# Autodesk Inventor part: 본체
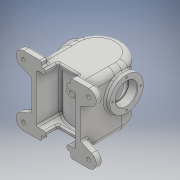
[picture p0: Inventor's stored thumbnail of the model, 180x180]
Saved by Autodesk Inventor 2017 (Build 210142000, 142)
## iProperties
Part Number: 본체
Material: 일반
Document SubType Name: Modeling
Designer: user
Density: 1 g/cm^3
Appearance: 기본값
Mass: 513.52 g
Surface Area: 1149.35 cm^2
Volume: 513.52 cm^3
Author: user
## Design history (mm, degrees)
sketch "스케치2"
  geometry: L1 (76, 0)-(76, -114); L2 (76, 0)-(121, 0); L3 (121, 0)-(121, -108); L4 (121, -108)-(104.5, -108); L5 (104.5, -108)-(104.5, -114); L6 (104.5, -114)-(92.5, -114); L7 (76, -9)-(112, -9); L8 (112, -9)-(112, -99); L9 (112, -99)-(92.5, -99); L10 (92.5, -99)-(92.5, -114); L11 (92.5, -114)-(76, -114); L12 (76, 0)-(76, -9); 1 further point
  constraints: 24 end point, 9 perpendicular, 2 horizontal, 1 collinear, 1 point on line, 1 vertical
  dimensions: "d3" = 76 distance from line of point (0, 0) L1; "d4" = 90 diameter of L3 L1; "d5" = 114 distance of L1.start L1.end; "d6" = 108 distance between parallel lines of L2 L4; "d7" = 57 diameter of L5 L1; "d8" = 0 distance from line of point (0, 0) L2; "d9" = 9 distance between parallel lines of L4 L9; "d10" = 9 distance between parallel lines of L2 L7; "d11" = 9 distance between parallel lines of L8 L3; "d12" = 33 diameter of L10 L1
revolve "회전1" sketch "스케치2" stored, may be unused: angle "d13" = 90 deg
node "작업 평면1"
sketch "스케치4"
  geometry: L1 (47.5, -114)-(104.5, -114) reference; C1 r 31 at (76, -40); 1 further point
  constraints: 1 centre point
  dimensions: "d15" = 62 diameter of C1; "d16" = 74 distance from line of L1 C1.centre; "d17" = 76 horizontal distance of point (0, 0) C1.centre
extrude "돌출1" join sketch "스케치4" stored distance "d18" = 10; taper "d19" = 0 deg
hole "구멍1" diameter "d22" = 35; stored, may be unused: countersink angle "d26" = 90 deg, drill point angle "d28" = 0 deg; dims "d20" = 10, "d21" = 10, "d23" = 6, "d24" = 40, "d25" = 16, "d27" = 8
node "작업 평면2"
sketch "스케치5"
  geometry: L1 (-28.5, -114)-(28.5, -114) reference; C1 r 7.5 at (0, -40); 1 further point
  constraints: 1 centre point, 1 vertical alignment
  dimensions: "d30" = 15 diameter of C1; "d31" = 74 distance from line of C1.centre L1
extrude "돌출2" join sketch "스케치5" stored distance "d32" = 10; taper "d33" = 0 deg
node "작업 평면3"
hole "구멍2" diameter "d37" = 5.188; stored, may be unused: countersink angle "d41" = 90 deg, drill point angle "d43" = 118 deg; dims "d35" = 10, "d36" = 10, "d38" = 12, "d39" = 40, "d40" = 16, "d42" = 16
sketch "스케치10" dims "d56" = 10, "d60" = 10
  geometry: L1 (74, 10)-(-74, 10); L2 (-74, 10)-(-74, -118); L3 (-74, -118)-(74, -118); L4 (74, -118)-(74, 10); L5 (-45, 0)-(45, 0) reference; L6 (60, 10)-(-60, 10); L7 (60, -118)-(-60, -118); L8 (74, -4)-(74, -104); L9 (-74, -4)-(-74, -104); A1 r 14 centre (60, -4) between (60, 10) and (74, -4); A2 r 14 centre (-60, -4) between (-60, 10) and (-74, -4); A3 r 14 centre (60, -104) between (60, -118) and (74, -104); A4 r 14 centre (-60, -104) between (-60, -118) and (-74, -104); 1 further point
  constraints: 16 end point, 8 point on circle, 8 point on line, 4 centre point, 2 horizontal, 2 parallel, 1 perpendicular, 1 vertical, 6 other
  dimensions: "d44" = 128 distance between parallel lines of L3 L1; "d45" = 148 distance of L1.start L1.end; "d46" = 74 distance from line of point (0, 0) L4; "d47" = 10 distance between parallel lines of L5 L1; "d48" = 28 diameter of A1; "d49" = 60 horizontal distance of point (0, 0) A1.centre; "d50" = 14 distance from line of L1 A1.centre; "d53" = 120 distance of A1.centre A2.centre; "d63" = 100 distance of A1.centre A3.centre
extrude "돌출3" join sketch "스케치10" distance "d65" = 12; taper "d66" = 0 deg
sketch "스케치13"
  geometry: L1 (74, 104)-(74, 4) reference; L2 (60, -10)-(-60, -10) reference; L3 (-74, 4)-(-74, 104) reference; L4 (-60, 118)-(60, 118) reference; L5 (-45, 0)-(45, 0); L6 (45, 0)-(45, 108); L7 (45, 108)-(-45, 108); L8 (-45, 108)-(-45, 0); L9 (-36, 9)-(36, 9); L10 (36, 9)-(36, 99); L11 (36, 99)-(-36, 99); L12 (-36, 99)-(-36, 9); A1 r 14 centre (60, 4) between (60, -10) and (74, 4) reference; A2 r 14 centre (-60, 4) between (-74, 4) and (-60, -10) reference; A3 r 14 centre (-60, 104) between (-60, 118) and (-74, 104) reference; A4 r 14 centre (60, 104) between (74, 104) and (60, 118) reference; 1 further point
  constraints: 16 end point, 4 parallel, 2 perpendicular, 1 horizontal, 3 other
  dimensions: "d67" = 10 distance between parallel lines of L2 L5; "d68" = 45 distance from line of point (0, 0) L8; "d69" = 45 distance from line of L6 point (0, 0); "d70" = 10 distance between parallel lines of L4 L7; "d71" = 9 distance between parallel lines of L8 L12
  node "절단 모서리 투영2"
extrude "돌출4" join sketch "스케치13" stored distance "d72" = 12; taper "d73" = 0 deg; dims "d3" = 76, "d4" = 90, "d5" = 114, "d6" = 108, "d7" = 57, "d8" = 0, "d9" = 9, "d10" = 9, "d11" = 9, "d12" = 33
sketch "스케치14"
  geometry: L1 (-78, -64)-(50, -64) reference; L2 (50, -64)-(50, -76) reference; L3 (50, -76)-(-78, -76) reference; L4 (-78, -76)-(-78, -64) reference; C1 r 31 at (0, 0) reference; C2 r 20 at (0, 0) reference; 1 further point
hole "구멍3" sketch "스케치14" at (0, 0) diameter "d74" = 40; stored, may be unused: countersink angle "d78" = 90 deg, drill point angle "d80" = 0 deg; dims "d75" = 12, "d76" = 40, "d77" = 16, "d79" = 16
extrude "돌출5" cut sketch "스케치13" stored distance "d81" = 12; taper "d82" = 0 deg
fillet "모깎기1" dims "d83" = 12
sketch "스케치15"
  geometry: L1 (40, -23)-(80, -23); L2 (80, -23)-(80, 23); L3 (80, 23)-(40, 23); L4 (40, 23)-(40, -23); L5 (40, -23)-(80, 23); L6 (80, -23)-(40, 23); L7 (0, 0)-(120, 0) reference; 1 further point
  constraints: 12 end point, 2 midpoint, 2 parallel, 1 horizontal, 1 perpendicular
  dimensions: "d84" = 23 distance between parallel lines of L3 L7; "d85" = 40 distance of L1.start L1.end
extrude "돌출6" cut sketch "스케치15" stored distance "d86" = 12; taper "d87" = 0 deg
sketch "스케치16"
  geometry: L1 (80, 0)-(80, 12) reference; L2 (80, 12)-(120, 12) reference; L3 (120, 0)-(120, 12) reference; L4 (120, 0)-(80, 0) reference; L5 (40, 12)-(40, 0) reference; L6 (40, 0)-(0, 0) reference; L7 (0, 0)-(0, 12) reference; L8 (0, 12)-(40, 12) reference; L9 (33, -12)-(87, -12); L10 (87, -12)-(87, 12); L11 (87, 12)-(33, 12); L12 (33, 12)-(33, -12); L13 (33, -12)-(87, 12); L14 (87, -12)-(33, 12); L15 (15, 76)-(15, 12) reference; 1 further point
  constraints: 12 end point, 2 midpoint, 2 parallel, 1 horizontal, 1 perpendicular
  dimensions: "d88" = 12 distance from line of point (60, 0) L11; "d89" = 18 distance between parallel lines of L15 L12
extrude "돌출7" cut sketch "스케치16" stored distance "d90" = 12; taper "d91" = 0 deg
sketch "스케치17"
  geometry: L1 (-87, -12)-(-33, -12); L2 (-33, -12)-(-33, 12); L3 (-33, 12)-(-87, 12); L4 (-87, 12)-(-87, -12); L5 (-87, -12)-(-33, 12); L6 (-33, -12)-(-87, 12); L7 (-105, 62.696)-(-105, 12) reference; 1 further point
  constraints: 12 end point, 2 midpoint, 2 parallel, 1 horizontal, 1 perpendicular
  dimensions: "d92" = 12 distance from line of point (-60, 0) L3; "d93" = 18 distance between parallel lines of L7 L4
extrude "돌출8" cut sketch "스케치17" stored distance "d94" = 12; taper "d95" = 0 deg
sketch "스케치18"
  geometry: L1 (-33, 108)-(-27, 108) reference; L2 (-27, 118)-(-27, 108) reference; L3 (-60, 118)-(-27, 118) reference; L4 (-74, 4)-(-74, 104) reference; L5 (-27, -10)-(-60, -10) reference; L6 (-27, 0)-(-27, -10) reference; L7 (-20, 0)-(-27, 0) reference; L8 (-20, 9)-(-20, 0) reference; L9 (-36, 9)-(-20, 9) reference; L10 (-36, 99)-(-36, 9) reference; L11 (-20, 99)-(-36, 99) reference; L12 (-20, 108)-(-20, 99) reference; L13 (-27, 108)-(-20, 108) reference; L14 (-45, 12)-(-45, 96) reference; L15 (-27, 0)-(-33, 0) reference; L16 (74, 104)-(74, 4) reference; L17 (60, -10)-(27, -10) reference; L18 (27, -10)-(27, 0) reference; L19 (33, 0)-(27, 0) reference; L20 (45, 96)-(45, 12) reference; L21 (27, 108)-(33, 108) reference; L22 (20, 108)-(27, 108) reference; L23 (20, 99)-(20, 108) reference; L24 (36, 99)-(20, 99) reference; L25 (36, 9)-(36, 99) reference; L26 (20, 9)-(36, 9) reference; L27 (20, 0)-(20, 9) reference; L28 (27, 0)-(20, 0) reference; L29 (27, 118)-(60, 118) reference; L30 (27, 108)-(27, 118) reference; L31 (65.693, 91.21)-(45, 82); L32 (45, 96)-(45, 12) reference; L33 (45, 26)-(65.693, 16.79); L34 (74, 4)-(74, 104) reference; L35 (74, 104)-(74, 4); L36 (45, 82)-(45, 26); A1 r 12 centre (-33, 96) between (-33, 108) and (-45, 96) reference; A2 r 14 centre (-60, 104) between (-60, 118) and (-74, 104) reference; A3 r 14 centre (-60, 4) between (-74, 4) and (-60, -10) reference; A4 r 12 centre (-33, 12) between (-45, 12) and (-33, 0) reference; A5 r 14 centre (60, 4) between (60, -10) and (74, 4) reference; A6 r 12 centre (33, 12) between (33, 0) and (45, 12) reference; A7 r 12 centre (33, 96) between (45, 96) and (33, 108) reference; A8 r 14 centre (60, 104) between (74, 104) and (60, 118) reference; A9 r 14 centre (60, 104) between (65.693, 91.21) and (74, 104); A10 r 14 centre (60, 4) between (60, -10) and (74, 4); A11 r 14 centre (60, 104) between (60, 118) and (65.693, 91.21); A12 r 14 centre (60, 104) between (74, 104) and (60, 118); A13 r 14 centre (60, 4) between (65.693, 16.79) and (60, -10); A14 r 14 centre (60, 4) between (74, 4) and (65.693, 16.79); 1 further point
  constraints: 12 point on circle, 11 end point, 6 centre point, 4 tangent, 2 coincident, 2 collinear, 2 point on line
  dimensions: "d98" = 36 distance from line of L29 L31.end; "d99" = 36 distance from line of L33.start L17
extrude "돌출9" cut sketch "스케치18" stored distance "d100" = 12; taper "d101" = 0 deg
sketch "스케치19"
  geometry: L1 (-33, 108)-(-27, 108) reference; L2 (-27, 118)-(-27, 108) reference; L3 (-60, 118)-(-27, 118) reference; L4 (-45, 82)-(-65.693, 91.21) reference; L5 (-45, 26)-(-45, 82) reference; L6 (-65.693, 16.79)-(-45, 26) reference; L7 (-27, -10)-(-60, -10) reference; L8 (-27, 0)-(-27, -10) reference; L9 (-27, 0)-(-33, 0) reference; L10 (-45, 12)-(-45, 26) reference; L11 (-45, 82)-(-45, 96) reference; L12 (-27, 108)-(-20, 108) reference; L13 (-20, 108)-(-20, 99) reference; L14 (-20, 99)-(-36, 99) reference; L15 (-36, 99)-(-36, 9) reference; L16 (-36, 9)-(-20, 9) reference; L17 (-20, 9)-(-20, 0) reference; L18 (-20, 0)-(-27, 0) reference; L19 (45, 96)-(45, 82) reference; L20 (65.693, 91.21)-(45, 82) reference; L21 (27, 118)-(60, 118) reference; L22 (27, 108)-(27, 118) reference; L23 (20, 108)-(27, 108) reference; L24 (20, 99)-(20, 108) reference; L25 (36, 99)-(20, 99) reference; L26 (36, 9)-(36, 99) reference; L27 (20, 9)-(36, 9) reference; L28 (20, 0)-(20, 9) reference; L29 (27, 0)-(20, 0) reference; L30 (27, -10)-(27, 0) reference; L31 (60, -10)-(27, -10) reference; L32 (45, 26)-(65.693, 16.79) reference; L33 (45, 26)-(45, 12) reference; L34 (33, 0)-(27, 0) reference; L35 (27, 108)-(33, 108) reference; L36 (45, 82)-(45, 26) reference; A1 r 12 centre (-33, 96) between (-33, 108) and (-45, 96) reference; A2 r 14 centre (-60, 104) between (-60, 118) and (-65.693, 91.21) reference; A3 r 14 centre (-60, 4) between (-65.693, 16.79) and (-60, -10) reference; A4 r 12 centre (-33, 12) between (-45, 12) and (-33, 0) reference; A5 r 12 centre (33, 96) between (45, 96) and (33, 108) reference; A6 r 14 centre (60, 104) between (65.693, 91.21) and (60, 118) reference; A7 r 14 centre (60, 4) between (60, -10) and (65.693, 16.79) reference; A8 r 12 centre (33, 12) between (33, 0) and (45, 12) reference; 1 further point
hole "구멍4" sketch "스케치19" at (-60, 4), (60, 4), (60, 104), (-60, 104) diameter "d102" = 6.6; stored, may be unused: countersink angle "d106" = 90 deg, drill point angle "d108" = 0 deg; dims "d103" = 12, "d104" = 18, "d105" = 2, "d107" = 16
sketch "스케치20"
  geometry: C1 r 20 at (0, 0); C2 r 31 at (0, 0) reference; 1 further point
  constraints: 1 centre point, 1 concentric
  dimensions: "d109" = 40 diameter of C1
extrude "돌출10" join sketch "스케치20" distance "d110" = 18; taper "d111" = 0 deg
hole "구멍5" diameter "d114" = 35; stored, may be unused: countersink angle "d118" = 90 deg, drill point angle "d120" = 0 deg; dims "d112" = 10, "d113" = 10, "d115" = 12, "d116" = 40, "d117" = 16, "d119" = 16
fillet "모깎기2" dims "d121" = 0.3
sketch "스케치21" dims "d122" = 52
  geometry: L1 (0, 0)-(0, 26); C1 r 20 at (0, 0) reference; C2 r 17.5 at (0, 0) reference; 6 further points
  constraints: 2 coincident, 2 end point, 1 vertical, 1 vertical alignment, 7 other
  dimensions: "d125" = 360 deg dimension on point (0, 0) point (0, 26) (derived)
hole "구멍6" sketch "스케치21" at (0, 26), (-26, 0), (0, -26), (26, 0) diameter "d127" = 3.242; stored, may be unused: countersink angle "d131" = 90 deg, drill point angle "d133" = 118 deg; dims "d128" = 8, "d129" = 40, "d130" = 16, "d132" = 10
sketch "스케치22" dims "d134" = 46
  geometry: L1 (0, 0)-(0, -23); C1 r 28.5 at (0, 0) reference; 6 further points
  constraints: 2 end point, 1 coincident, 1 vertical, 1 vertical alignment, 8 other
  dimensions: "d137" = 360 deg dimension on point (0, 0) point (0, -23) (derived)
hole "구멍7" sketch "스케치22" at (0, -23), (23, 0), (0, 23), (-23, 0) diameter "d139" = 3.242; stored, may be unused: countersink angle "d143" = 90 deg, drill point angle "d145" = 118 deg; dims "d140" = 8, "d141" = 40, "d142" = 16, "d144" = 10
fillet "모깎기3" dims "d146" = 3
fillet "모깎기4" dims "d147" = 3
fillet "모깎기5" dims "d148" = 3
fillet "모깎기6" dims "d149" = 3
fillet "모깎기7" dims "d150" = 3
fillet "모깎기8" dims "d151" = 3
fillet "모깎기9" dims "d152" = 3
sketch "스케치24" dims "d115" = 12
  geometry: L1 (35.676, 38.002)-(84.324, 38.002); L2 (84.324, 38.002)-(84.324, 31.998); L3 (84.324, 31.998)-(35.676, 31.998); L4 (35.676, 31.998)-(35.676, 38.002); L5 (35.676, 35)-(84.324, 35); L6 (60, 38.002)-(60, 31.998); L7 (90, 0)-(120, 0) reference; 1 further point
  constraints: 4 end point, 4 midpoint, 1 vertical alignment, 2 other
  dimensions: "d153" = 35 distance between parallel lines of L7 L5
feature "엠보싱1" sketch "스케치24" dims "d154" = 0.5, "d155" = 0
chamfer "모따기1" distance "d156" = 1; stored, may be unused: second distance "d157" = 2, angle "d158" = 45 deg
fillet "모깎기10" dims "d159" = 3
node "솔리드1"
mirror "미러1"
mirror "미러2"
mirror "미러3"
mirror "미러4"
mirror "미러5"
node "절단 모서리 투영3"
node "절단 모서리 투영4"
node "절단 모서리 투영5"
node "절단 모서리 투영6"
other parameters: "d14" = 54, "d29" = 125, "d34" = -49
